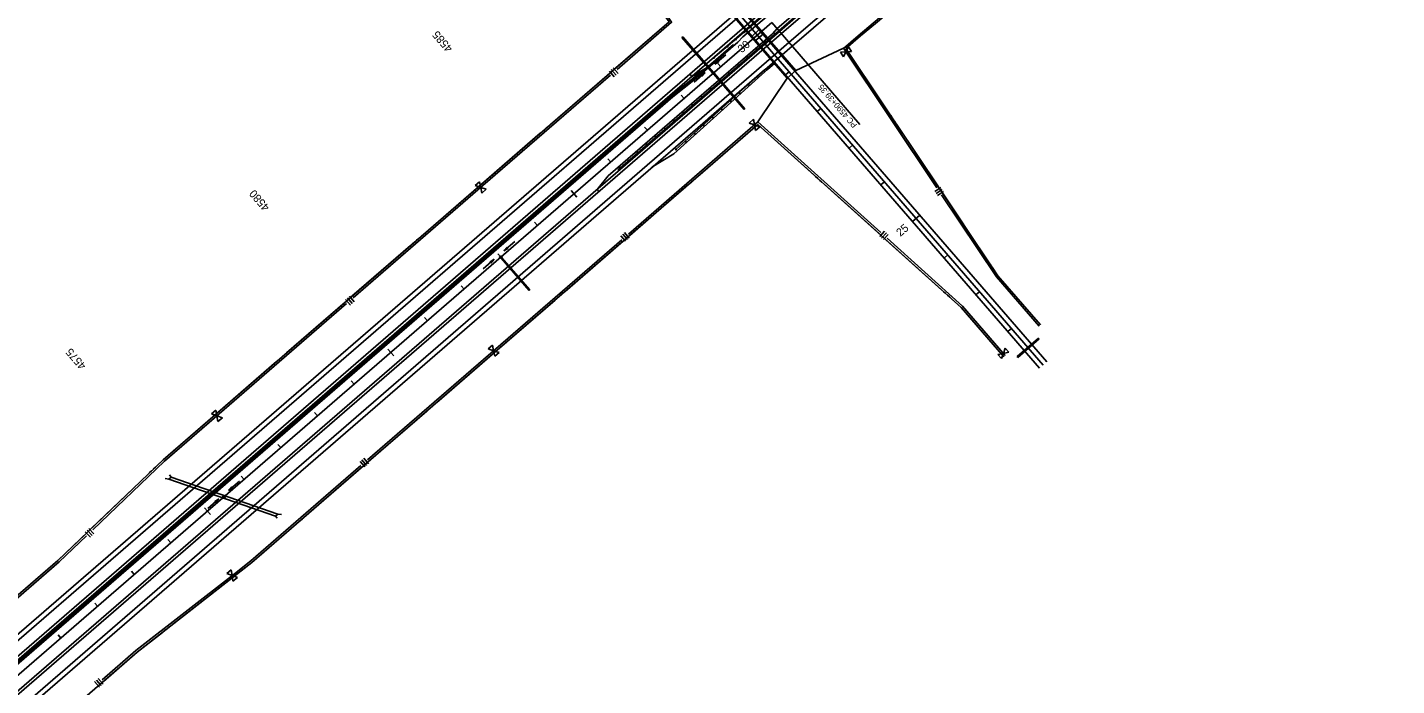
# Model space of a CAD drawing. Extents: x 192699 to 285914, y 194342 to 233219.
# Drawn here: x 205979 to 208803, y 205138 to 206496 of the extents above; entities that cross this region are included whole.
import ezdxf

# ---------------------------------------------------------------- set-up
doc = ezdxf.new("R2010")
doc.units = 0
for name, color, linetype in [('CENT LINE', 7, 'Continuous'), ('CONCRETE', 7, 'Continuous'), ('DRAINAGE', 7, 'Continuous'), ('DRAINAGE ARROWS', 7, 'Continuous'), ('GUARD RAILS', 7, 'Continuous'), ('GUARDRAIL', 7, 'Continuous'), ('R-W - CofA', 7, 'Continuous'), ('R_Draft', 7, 'Continuous'), ('R_Water Annot', 7, 'Continuous'), ('ROAD', 7, 'Continuous'), ('SHOULDER', 7, 'Continuous'), ('STATIONING1', 7, 'Continuous'), ('STATIONING2', 7, 'Continuous'), ('TEXT', 7, 'Continuous'), ('WRSF', 7, 'Continuous')]:
    doc.layers.add(name, color=color, linetype=linetype)

msp = doc.modelspace()

# ---------------------------------------------------------------- linework, layer by layer
at = {"layer": 'CENT LINE'}
for p, q in [((208073.9, 205799.3), (206788.6, 207284)), ((198833.2, 198989.9), (207514.6, 206505.5))]:
    msp.add_line(p, q, dxfattribs=at)
at = {"layer": 'CONCRETE'}
for p, q in [((207454.5, 206476.5), (207808.8, 206775.8)), ((207525.8, 206493.6), (207616.6, 206572.1)), ((207525.8, 206493.6), (207515.7, 206482.3)), ((207177.3, 206189.7), (207515.7, 206482.3)), ((207444.4, 206465.2), (207353.6, 206386.7)), ((207444.4, 206465.2), (207454.5, 206476.5)), ((207349.9, 206394.1), (207391.5, 206419.4)), ((207351.1, 206389.8), (207308.1, 206355.8)), ((207353.6, 206386.7), (207310.6, 206352.7)), ((207349.9, 206394.1), (207346, 206398.6)), ((207370.7, 206406.8), (207351.1, 206389.8)), ((203079, 202694.6), (207308.1, 206355.8)), ((203081.6, 202691.6), (207310.6, 206352.7)), ((207154, 206161.6), (207177.3, 206189.7)), ((207154, 206161.6), (207157.9, 206157.1))]:
    msp.add_line(p, q, dxfattribs=at)
at = {"layer": 'DRAINAGE'}
for p, q in [((206956.2, 206019.4), (207013.8, 205952.9)), ((206957.7, 206020.7), (207015.3, 205954.2)), ((208020.6, 205816.6), (208064.4, 205854.6)), ((208021.9, 205815.1), (208065.7, 205853.1)), ((206275.9, 205568.3), (206270.7, 205563.8)), ((206490.8, 205487.5), (206270.7, 205563.8)), ((206496.1, 205492), (206275.9, 205568.3)), ((206490.8, 205487.5), (206496.1, 205492))]:
    msp.add_line(p, q, dxfattribs=at)
for points in [[(207329.2, 206474.7), (207330.7, 206476)], [(207329.2, 206474.7), (207392, 206402.1)], [(207330.7, 206476), (207393.6, 206403.4)], [(207394.7, 206399), (207457.5, 206326.5)], [(207396.2, 206400.4), (207459, 206327.8)], [(207457.5, 206326.5), (207459, 206327.8)], [(207013.8, 205952.9), (207015.3, 205954.2)], [(208064.4, 205854.6), (208065.7, 205853.1)], [(208020.6, 205816.6), (208021.9, 205815.1)], [(206270.7, 205563.8), (206263.7, 205565.1)], [(206275.9, 205568.3), (206272.6, 205572.8)], [(206490.8, 205487.5), (206494.2, 205483.1)], [(206496.1, 205492), (206503.1, 205490.8)]]:
    msp.add_lwpolyline(points, dxfattribs=at)
for points in [[(207393.9, 206398.4), (207396.9, 206401), (207394.3, 206404), (207391.3, 206401.4)], [(206955.4, 206018.8), (206958.4, 206021.4), (206955.8, 206024.4), (206952.8, 206021.8)], [(206384.6, 205524.6), (206387.6, 205527.2), (206385, 205530.3), (206382, 205527.6)]]:
    msp.add_lwpolyline(points, close=True, dxfattribs=at)
at = {"layer": 'DRAINAGE ARROWS'}
for p, q in [((207403.5, 206427.4), (207396.9, 206419.7)), ((207405.5, 206425.1), (207396.9, 206419.7)), ((207403.7, 206427.2), (207398.2, 206420.8)), ((207405.3, 206425.3), (207398.2, 206420.8)), ((207403.8, 206427), (207399.5, 206421.9)), ((207405.1, 206425.5), (207399.5, 206421.9)), ((207404, 206426.8), (207400.7, 206423)), ((207405, 206425.7), (207400.7, 206423)), ((207404.2, 206426.6), (207402, 206424.1)), ((207404.8, 206425.9), (207402, 206424.1)), ((207404.3, 206426.4), (207403.3, 206425.2)), ((207404.6, 206426), (207403.3, 206425.2)), ((207405.5, 206425.1), (207403.5, 206427.4)), ((207368.5, 206397), (207377, 206402.4)), ((207370.4, 206394.8), (207368.5, 206397)), ((207368.6, 206396.9), (207375.8, 206401.3)), ((207368.8, 206396.7), (207374.5, 206400.2)), ((207369, 206396.5), (207373.2, 206399.1)), ((207369.1, 206396.3), (207371.9, 206398)), ((207369.3, 206396.1), (207370.7, 206396.9)), ((207369.6, 206395.7), (207370.7, 206396.9)), ((207369.8, 206395.5), (207371.9, 206398)), ((207369.9, 206395.3), (207373.2, 206399.1)), ((207370.1, 206395.2), (207374.5, 206400.2)), ((207370.3, 206395), (207375.8, 206401.3)), ((207370.4, 206394.8), (207377, 206402.4)), ((206968.4, 206042.2), (206961.8, 206034.5)), ((206968.5, 206042), (206963.1, 206035.6)), ((206968.7, 206041.8), (206964.4, 206036.7)), ((206968.9, 206041.6), (206965.6, 206037.8)), ((206969, 206041.4), (206966.9, 206038.9)), ((206969.2, 206041.3), (206968.2, 206040)), ((206970.4, 206039.9), (206968.4, 206042.2)), ((206933.4, 206011.9), (206941.9, 206017.3)), ((206933.5, 206011.7), (206940.7, 206016.2)), ((206933.7, 206011.5), (206939.4, 206015.1)), ((206933.9, 206011.3), (206938.1, 206014)), ((206934, 206011.1), (206936.8, 206012.9)), ((206934.7, 206010.4), (206936.8, 206012.9)), ((206934.8, 206010.2), (206938.1, 206014)), ((206935, 206010), (206939.4, 206015.1)), ((206935.2, 206009.8), (206940.7, 206016.2)), ((206935.3, 206009.6), (206941.9, 206017.3)), ((206970.4, 206039.9), (206961.8, 206034.5)), ((206970.2, 206040.1), (206963.1, 206035.6)), ((206970, 206040.3), (206964.4, 206036.7)), ((206969.9, 206040.5), (206965.6, 206037.8)), ((206969.7, 206040.7), (206966.9, 206038.9)), ((206969.5, 206040.9), (206968.2, 206040)), ((206935.3, 206009.6), (206933.4, 206011.9)), ((206934.2, 206010.9), (206935.5, 206011.8)), ((206934.5, 206010.6), (206935.5, 206011.8)), ((206400.7, 205548.1), (206394.1, 205540.4)), ((206402.6, 205545.8), (206394.1, 205540.4)), ((206400.8, 205547.9), (206395.4, 205541.5)), ((206402.5, 205546), (206395.4, 205541.5)), ((206401, 205547.7), (206396.7, 205542.6)), ((206402.3, 205546.2), (206396.7, 205542.6)), ((206401.2, 205547.5), (206397.9, 205543.7)), ((206402.1, 205546.4), (206397.9, 205543.7)), ((206401.3, 205547.3), (206399.2, 205544.8)), ((206402, 205546.6), (206399.2, 205544.8)), ((206401.5, 205547.1), (206400.5, 205545.9)), ((206401.8, 205546.8), (206400.5, 205545.9)), ((206402.6, 205545.8), (206400.7, 205548.1)), ((206365.6, 205517.8), (206374.2, 205523.2)), ((206367.6, 205515.5), (206365.6, 205517.8)), ((206365.8, 205517.6), (206372.9, 205522.1)), ((206366, 205517.4), (206371.6, 205521)), ((206366.1, 205517.2), (206370.4, 205519.9)), ((206366.3, 205517), (206369.1, 205518.8)), ((206366.5, 205516.8), (206367.8, 205517.7)), ((206366.8, 205516.5), (206367.8, 205517.7)), ((206366.9, 205516.3), (206369.1, 205518.8)), ((206367.1, 205516.1), (206370.4, 205519.9)), ((206367.3, 205515.9), (206371.6, 205521)), ((206367.4, 205515.7), (206372.9, 205522.1)), ((206367.6, 205515.5), (206374.2, 205523.2))]:
    msp.add_line(p, q, dxfattribs=at)
at = {"layer": 'GUARD RAILS'}
for p, q in [((207393.6, 206432.3), (207797.5, 206773.6)), ((207196.8, 206201.3), (207575.1, 206528.3))]:
    msp.add_line(p, q, dxfattribs=at)
for centre in [(207440.7, 206470.8), (207458.5, 206485.8), (207502.3, 206466.3), (207521.2, 206482.7), (207423, 206455.8), (207483.4, 206450), (207394.9, 206432.5), (207445.6, 206417.3), (207464.5, 206433.7), (207407.7, 206384.6), (207426.7, 206401), (207369.9, 206351.9), (207388.8, 206368.3), (207351, 206335.6), (207313.2, 206302.9), (207332.1, 206319.2), (207275.3, 206270.2), (207294.3, 206286.5), (207256.4, 206253.8), (207218.6, 206221.1), (207237.5, 206237.5), (207201, 206205.9)]:
    msp.add_circle(centre, 0.75, dxfattribs=at)
at = {"layer": 'GUARDRAIL'}
for p, q in [((207471.8, 206476.4), (207490, 206492.1)), ((207479.7, 206467.4), (207497.8, 206483.1)), ((207517.6, 206423.5), (207535.8, 206439.2)), ((207499.6, 206407.9), (207384.5, 206308.3))]:
    msp.add_line(p, q, dxfattribs=at)
at = {"layer": 'R-W - CofA'}
for p, q in [((207655.8, 206444.5), (207667.3, 206445.2)), ((207662.2, 206434.9), (207655.8, 206444.5)), ((207667.3, 206445.2), (207662.2, 206434.9)), ((207667.3, 206445.2), (207672.4, 206455.6)), ((207678.9, 206446), (207667.3, 206445.2)), ((207672.4, 206455.6), (207678.9, 206446)), ((207183.5, 206408.8), (207193.5, 206397.3)), ((207187.4, 206412.1), (207197.3, 206400.6)), ((207179.7, 206405.5), (207189.6, 206394)), ((207467.5, 206298.4), (207476.4, 206306.1)), ((207478.7, 206294.5), (207467.5, 206298.4)), ((207476.4, 206306.1), (207478.7, 206294.5)), ((207480.9, 206283), (207478.7, 206294.5)), ((207478.7, 206294.5), (207489.8, 206290.7)), ((207489.8, 206290.7), (207480.9, 206283)), ((206902.9, 206169.5), (206912, 206177.3)), ((206914.2, 206165.6), (206902.9, 206169.5)), ((206912, 206177.3), (206914.2, 206165.6)), ((206916.5, 206153.9), (206914.2, 206165.6)), ((206914.2, 206165.6), (206925.5, 206161.7)), ((206925.5, 206161.7), (206916.5, 206153.9)), ((207850.8, 206157.4), (207863.1, 206165.6)), ((207853.5, 206153.4), (207865.8, 206161.5)), ((207856.3, 206149.3), (207868.5, 206157.5)), ((207207, 206069.3), (207216.9, 206057.9)), ((207210.8, 206072.6), (207220.6, 206061.2)), ((207747, 206075.4), (207737.2, 206064.4)), ((207750.7, 206072.1), (207740.8, 206061.1)), ((207203.2, 206066), (207213.1, 206054.7)), ((207754.3, 206068.8), (207744.5, 206057.9)), ((206635.6, 205934.5), (206645.6, 205923)), ((206639.5, 205937.8), (206649.4, 205926.3)), ((206643.3, 205941.1), (206653.2, 205929.6)), ((206929.6, 205832.7), (206938.5, 205840.4)), ((206940.7, 205828.9), (206929.6, 205832.7)), ((206938.5, 205840.4), (206940.7, 205828.9)), ((206943, 205817.3), (206940.7, 205828.9)), ((206940.7, 205828.9), (206951.9, 205825)), ((206951.9, 205825), (206943, 205817.3)), ((207980.7, 205821.3), (207992.1, 205823.4)), ((207988.3, 205812.5), (207980.7, 205821.3)), ((207992.1, 205823.4), (207988.3, 205812.5)), ((207992.1, 205823.4), (207995.9, 205834.4)), ((208003.5, 205825.6), (207992.1, 205823.4)), ((207995.9, 205834.4), (208003.5, 205825.6)), ((206358.9, 205698.5), (206367.9, 205706.3)), ((206367.9, 205706.3), (206370.2, 205694.6)), ((206370.2, 205694.6), (206358.9, 205698.5)), ((206372.4, 205682.9), (206370.2, 205694.6)), ((206370.2, 205694.6), (206381.4, 205690.7)), ((206381.4, 205690.7), (206372.4, 205682.9)), ((206665.3, 205600.3), (206675.2, 205589)), ((206669.1, 205603.6), (206678.9, 205592.3)), ((206672.9, 205606.9), (206682.7, 205595.5)), ((206098.8, 205455.3), (206109.3, 205444.3)), ((206102.5, 205458.8), (206113, 205447.8)), ((206106.1, 205462.3), (206116.6, 205451.3)), ((206390.5, 205369.6), (206399.8, 205376.9)), ((206401.4, 205365.2), (206390.5, 205369.6)), ((206399.8, 205376.9), (206401.4, 205365.2)), ((206403.1, 205353.5), (206401.4, 205365.2)), ((206401.4, 205365.2), (206412.4, 205360.8)), ((206412.4, 205360.8), (206403.1, 205353.5)), ((206117.9, 205146.3), (206127.7, 205134.9)), ((206121.7, 205149.5), (206131.5, 205138.2)), ((206125.4, 205152.8), (206135.3, 205141.4))]:
    msp.add_line(p, q, dxfattribs=at)
for points in [[(207195.4, 206409), (207307.8, 206506.3), (207190, 206682.7)], [(203774, 203432.6), (206042.1, 205396.1), (206259.1, 205603.8), (207302.5, 206507.1)], [(207192.7, 206412.1), (207302.5, 206507.1), (207294.2, 206519.4)], [(207564, 206406.6), (207662.5, 206452.5)], [(207854.7, 206164.8), (207662.5, 206452.5)], [(208068.5, 205881.9), (207980.8, 205983.3), (207667.4, 206452.2)], [(207756.8, 206318.4), (207667.4, 206452.2)], [(206918.7, 206169.5), (207181.6, 206397.1)], [(207058, 206295.4), (207179, 206400.1)], [(207485.7, 206300.7), (207545.9, 206390.9)], [(203710.8, 203047.2), (206205.8, 205207.1), (206442.4, 205392.1), (207485.7, 206295.4)], [(207218.7, 206069.5), (207485.7, 206300.7)], [(207361.7, 206188), (207485.7, 206295.4)], [(207485.7, 206300.7), (207739.2, 206072.5)], [(207485.7, 206295.4), (207905.2, 205917.8), (207992.9, 205816.5)], [(207485.7, 206295.4), (207601.1, 206191.5)], [(207762.9, 206309.3), (207759.6, 206314.3)], [(207769, 206300.1), (207765.7, 206305.1)], [(207858, 206167), (207771.8, 206296)], [(206916.1, 206172.5), (207037, 206277.2)], [(207040.9, 206280.6), (207045.6, 206284.7)], [(207049.5, 206288), (207054.1, 206292.1)], [(207353.2, 206180.7), (207357.9, 206184.7)], [(207604.8, 206188.2), (207609.3, 206184.2)], [(206651.3, 205938), (206918.7, 206169.5)], [(206790.6, 206063.9), (206916.1, 206172.5)], [(207221.4, 206066.5), (207340.9, 206170)], [(207344.8, 206173.3), (207349.4, 206177.3)], [(207613, 206180.8), (207617.4, 206176.8)], [(207621.2, 206173.5), (207736.5, 206069.6)], [(208065.5, 205879.4), (207977.7, 205980.9), (207864.6, 206150.1)], [(207954.1, 206023.3), (207867.8, 206152.3)], [(206648.7, 205941.1), (206769.6, 206045.8)], [(206773.5, 206049.1), (206778.2, 206053.2)], [(206782.1, 206056.5), (206786.7, 206060.6)], [(206945.2, 205832.7), (207205.1, 206057.7)], [(207088.2, 205951.2), (207207.7, 206054.7)], [(207749.7, 206057.8), (207865.1, 205953.9)], [(207752.3, 206060.7), (207908, 205920.6), (207995.9, 205819.1)], [(207960.2, 206014.1), (207956.8, 206019.1)], [(207966.3, 206005), (207962.9, 206010)], [(208068.5, 205881.9), (207980.8, 205983.3), (207969, 206000.9)], [(206514, 205824.4), (206634.9, 205929.1)], [(206947.8, 205829.7), (207067.4, 205933.2)], [(207071.2, 205936.5), (207075.9, 205940.5)], [(207079.7, 205943.9), (207084.3, 205947.9)], [(207868.8, 205950.6), (207873.2, 205946.6)], [(207876.9, 205943.2), (207881.4, 205939.2)], [(207885.1, 205935.9), (207905.2, 205917.8), (207992.9, 205816.5)], [(206374.7, 205698.5), (206637.6, 205926.1)], [(206505.4, 205817), (206510.1, 205821.1)], [(206680.8, 205603.8), (206945.2, 205832.7)], [(206823.8, 205722.3), (206947.8, 205829.7)], [(206372, 205701.6), (206493, 205806.3)], [(206496.9, 205809.6), (206501.5, 205813.7)], [(206683.5, 205600.8), (206803, 205704.3)], [(206806.9, 205707.7), (206811.5, 205711.7)], [(206815.3, 205715), (206819.9, 205719)], [(206114.3, 205459.6), (206261.9, 205600.8), (206374.7, 205698.5)], [(206247.1, 205592.3), (206259.1, 205603.8), (206372, 205701.6)], [(206406.1, 205368.8), (206439.9, 205395.2), (206667.2, 205592)], [(206111.5, 205462.5), (206227.1, 205573.1)], [(206230.8, 205576.7), (206235.2, 205581)], [(206239, 205584.5), (206243.4, 205588.8)], [(206550.3, 205485.5), (206669.8, 205589)], [(206541.8, 205478.2), (206546.4, 205482.2)], [(205980, 205342.3), (206042.1, 205396.1), (206098.3, 205449.9)], [(206408.6, 205365.7), (206442.4, 205392.1), (206529.5, 205467.5)], [(206533.3, 205470.9), (206538, 205474.9)], [(205840.7, 205216.4), (206044.9, 205393.1), (206101.1, 205447)], [(206133.4, 205149.8), (206203.2, 205210.2), (206406.1, 205368.8)], [(206279.3, 205264.6), (206408.6, 205365.7)], [(206261.7, 205250.8), (206266.5, 205254.6)], [(206270.5, 205257.7), (206275.3, 205261.5)], [(206136, 205146.7), (206205.8, 205207.1), (206257.7, 205247.7)]]:
    msp.add_lwpolyline(points, dxfattribs=at)
for radius, end in [(11322.5, 130.49311), (11319.2, 130.47508), (11319.2, 130.47508)]:
    msp.add_arc((215014.8, 197841.9), radius, 117.58007, end, dxfattribs=at)
at = {"layer": 'R_Draft'}
for p, q in [((207503.5, 206411.2), (207484.6, 206394.9)), ((207505.8, 206408.6), (207486.9, 206392.2)), ((207503.5, 206411.2), (207517.6, 206423.5)), ((207505.8, 206408.6), (207519.9, 206420.9)), ((207484.6, 206394.9), (207354.6, 206277.7)), ((207486.9, 206392.3), (207394, 206308.6)), ((207394, 206308.6), (207312.3, 206234.9)), ((207354.6, 206277.7), (207317.4, 206244.2)), ((207315.5, 206243.8), (207317.4, 206244.2)), ((207315.5, 206243.8), (207316.8, 206242.3)), ((207316.8, 206242.3), (207317.4, 206244.2)), ((207312.3, 206234.9), (207267.2, 206207.3))]:
    msp.add_line(p, q, dxfattribs=at)
for centre in [(207504, 206410.7), (207506.3, 206412.7), (207508.7, 206414.8), (207511.1, 206416.8), (207512.2, 206417.8), (207513.4, 206418.9), (207514.6, 206419.9), (207515.8, 206420.9), (207517, 206421.9), (207485, 206394.3), (207499.2, 206406.6), (207447.9, 206360.8), (207466.5, 206377.6), (207410.8, 206327.3), (207429.3, 206344.1), (207392.2, 206310.6), (207355, 206277.1), (207373.6, 206293.9), (207336.5, 206260.4)]:
    msp.add_circle(centre, 0.75, dxfattribs=at)
at = {"layer": 'R_Water Annot'}
for p, q in [((207419.6, 206439.3), (207396.9, 206419.7)), ((207403.5, 206427.4), (207396.9, 206419.7)), ((207405.5, 206425.1), (207396.9, 206419.7)), ((207403.7, 206427.2), (207398.2, 206420.8)), ((207405.3, 206425.3), (207398.2, 206420.8)), ((207403.8, 206427), (207399.5, 206421.9)), ((207405.1, 206425.5), (207399.5, 206421.9)), ((207404, 206426.8), (207400.7, 206423)), ((207405, 206425.7), (207400.7, 206423)), ((207404.2, 206426.6), (207402, 206424.1)), ((207404.8, 206425.9), (207402, 206424.1)), ((207404.3, 206426.4), (207403.3, 206425.2)), ((207404.6, 206426), (207403.3, 206425.2)), ((207405.5, 206425.1), (207403.5, 206427.4)), ((207354.3, 206382.8), (207377, 206402.4)), ((207368.5, 206397), (207377, 206402.4)), ((207370.4, 206394.8), (207368.5, 206397)), ((207368.6, 206396.9), (207375.8, 206401.3)), ((207368.8, 206396.7), (207374.5, 206400.2)), ((207369, 206396.5), (207373.2, 206399.1)), ((207369.1, 206396.3), (207371.9, 206398)), ((207369.3, 206396.1), (207370.7, 206396.9)), ((207369.6, 206395.7), (207370.7, 206396.9)), ((207369.8, 206395.5), (207371.9, 206398)), ((207369.9, 206395.3), (207373.2, 206399.1)), ((207370.1, 206395.2), (207374.5, 206400.2)), ((207370.3, 206395), (207375.8, 206401.3)), ((207370.4, 206394.8), (207377, 206402.4)), ((206984.5, 206054.2), (206961.8, 206034.5)), ((206968.4, 206042.2), (206961.8, 206034.5)), ((206968.5, 206042), (206963.1, 206035.6)), ((206968.7, 206041.8), (206964.4, 206036.7)), ((206968.9, 206041.6), (206965.6, 206037.8)), ((206969, 206041.4), (206966.9, 206038.9)), ((206969.2, 206041.3), (206968.2, 206040)), ((206970.4, 206039.9), (206968.4, 206042.2)), ((206919.2, 205997.7), (206941.9, 206017.3)), ((206933.4, 206011.9), (206941.9, 206017.3)), ((206933.5, 206011.7), (206940.7, 206016.2)), ((206933.7, 206011.5), (206939.4, 206015.1)), ((206933.9, 206011.3), (206938.1, 206014)), ((206934, 206011.1), (206936.8, 206012.9)), ((206934.7, 206010.4), (206936.8, 206012.9)), ((206934.8, 206010.2), (206938.1, 206014)), ((206935, 206010), (206939.4, 206015.1)), ((206935.2, 206009.8), (206940.7, 206016.2)), ((206935.3, 206009.6), (206941.9, 206017.3)), ((206970.4, 206039.9), (206961.8, 206034.5)), ((206970.2, 206040.1), (206963.1, 206035.6)), ((206970, 206040.3), (206964.4, 206036.7)), ((206969.9, 206040.5), (206965.6, 206037.8)), ((206969.7, 206040.7), (206966.9, 206038.9)), ((206969.5, 206040.9), (206968.2, 206040)), ((206935.3, 206009.6), (206933.4, 206011.9)), ((206934.2, 206010.9), (206935.5, 206011.8)), ((206934.5, 206010.6), (206935.5, 206011.8)), ((206416.7, 205560.1), (206394.1, 205540.4)), ((206400.7, 205548.1), (206394.1, 205540.4)), ((206402.6, 205545.8), (206394.1, 205540.4)), ((206400.8, 205547.9), (206395.4, 205541.5)), ((206402.5, 205546), (206395.4, 205541.5)), ((206401, 205547.7), (206396.7, 205542.6)), ((206402.3, 205546.2), (206396.7, 205542.6)), ((206401.2, 205547.5), (206397.9, 205543.7)), ((206402.1, 205546.4), (206397.9, 205543.7)), ((206401.3, 205547.3), (206399.2, 205544.8)), ((206402, 205546.6), (206399.2, 205544.8)), ((206401.5, 205547.1), (206400.5, 205545.9)), ((206401.8, 205546.8), (206400.5, 205545.9)), ((206402.6, 205545.8), (206400.7, 205548.1)), ((206351.5, 205503.6), (206374.2, 205523.2)), ((206365.6, 205517.8), (206374.2, 205523.2)), ((206367.6, 205515.5), (206365.6, 205517.8)), ((206365.8, 205517.6), (206372.9, 205522.1)), ((206366, 205517.4), (206371.6, 205521)), ((206366.1, 205517.2), (206370.4, 205519.9)), ((206366.3, 205517), (206369.1, 205518.8)), ((206366.5, 205516.8), (206367.8, 205517.7)), ((206366.8, 205516.5), (206367.8, 205517.7)), ((206366.9, 205516.3), (206369.1, 205518.8)), ((206367.1, 205516.1), (206370.4, 205519.9)), ((206367.3, 205515.9), (206371.6, 205521)), ((206367.4, 205515.7), (206372.9, 205522.1)), ((206367.6, 205515.5), (206374.2, 205523.2))]:
    msp.add_line(p, q, dxfattribs=at)
at = {"layer": 'ROAD'}
for p, q in [((208081.5, 205805.9), (206796.1, 207290.6)), ((208066.3, 205792.8), (206781, 207277.5)), ((207545.9, 206390.9), (207405.6, 206552.9)), ((207564, 206406.6), (207423.8, 206568.6)), ((198797.8, 199030.7), (207479.2, 206546.3)), ((198813.5, 199012.5), (207494.9, 206528.2)), ((198852.8, 198967.2), (207534.2, 206482.8)), ((198868.5, 198949), (207549.9, 206464.7))]:
    msp.add_line(p, q, dxfattribs=at)
msp.add_lwpolyline([(207545.9, 206390.9), (207564, 206406.6)], dxfattribs=at)
for radius in [11429.2, 11405.2]:
    msp.add_arc((215014.8, 197841.9), radius, 112.21667, 130.88334, dxfattribs=at)
at = {"layer": 'SHOULDER'}
for p, q in [((203018.9, 202698.1), (207472.7, 206553.9)), ((203077.6, 202696.1), (207498.9, 206523.7)), ((203109.1, 202659.8), (207530.3, 206487.4)), ((203088.4, 202589), (207556.5, 206457.1))]:
    msp.add_line(p, q, dxfattribs=at)
for radius in [11435.2, 11395.2]:
    msp.add_arc((215014.8, 197841.9), radius, 112.21667, 130.88334, dxfattribs=at)
at = {"layer": 'STATIONING1'}
msp.add_line((207479, 206486.6), (207490.7, 206472.9), dxfattribs=at)
for points in [[(207403.3, 206421.1), (207409.2, 206414.3)], [(207327.7, 206355.7), (207333.6, 206348.9)], [(207252.1, 206290.2), (207258, 206283.4)], [(207176.5, 206224.8), (207182.4, 206218)], [(207100.9, 206159.3), (207112.7, 206145.7)], [(207025.3, 206093.9), (207031.2, 206087)], [(206949.7, 206028.4), (206955.6, 206021.6)], [(206874.1, 205962.9), (206880, 205956.1)], [(206798.5, 205897.5), (206804.4, 205890.7)], [(206722.9, 205832), (206734.7, 205818.4)], [(206647.3, 205766.6), (206653.2, 205759.8)], [(206571.7, 205701.1), (206577.6, 205694.3)], [(206496.1, 205635.7), (206502, 205628.9)], [(206420.5, 205570.2), (206426.4, 205563.4)], [(206344.9, 205504.8), (206356.7, 205491.2)], [(206269.3, 205439.3), (206275.2, 205432.5)], [(206193.7, 205373.9), (206199.6, 205367.1)], [(206118.1, 205308.4), (206124, 205301.6)], [(206042.5, 205243), (206048.4, 205236.2)]]:
    msp.add_lwpolyline(points, dxfattribs=at)
at = {"layer": 'STATIONING2'}
for points in [[(207478, 206473.9), (207491.6, 206485.6)], [(207478, 206473.9), (207491.6, 206485.6)], [(207543.5, 206398.3), (207550.3, 206404.2)], [(207608.9, 206322.7), (207615.7, 206328.6)], [(207674.4, 206247.1), (207681.2, 206252.9)], [(207739.8, 206171.5), (207746.6, 206177.3)], [(207805.3, 206095.8), (207818.9, 206107.6)], [(207870.9, 206020.5), (207877.7, 206026.4)], [(207936.2, 205944.6), (207943, 205950.5)], [(208001.6, 205869), (208008.5, 205874.9)]]:
    msp.add_lwpolyline(points, dxfattribs=at)
at = {"layer": 'TEXT'}
msp.add_lwpolyline([(207514.6, 206505.5), (207696.2, 206295.7)], dxfattribs=at)
at = {"layer": 'WRSF'}
for p, q in [((207435.6, 206460.2), (207352.4, 206388.3)), ((207352.3, 206388.2), (207309.3, 206354.3)), ((203046.3, 202663.7), (207309.3, 206354.3))]:
    msp.add_line(p, q, dxfattribs=at)

# ---------------------------------------------------------------- texts
at = {"layer": 'STATIONING1'}
for s, p in [('4585', (206857.5, 206453.1)), ('4580', (206479.9, 206125.3)), ('4575', (206101.5, 205798.5))]:
    msp.add_text(s, height=16.5, rotation=130.8833, dxfattribs=at).set_placement(p)
at = {"layer": 'STATIONING2'}
for s, p in [('30', (207452.6, 206442.1)), ('25', (207779.7, 206063.4))]:
    msp.add_text(s, height=16.5, rotation=40.8833, dxfattribs=at).set_placement(p)
at = {"layer": 'TEXT'}
msp.add_text('PC 4590+39.35', height=12, rotation=130.8833, dxfattribs=at).set_placement((207691.3, 206294.9))

doc.saveas('drawing.dxf')
